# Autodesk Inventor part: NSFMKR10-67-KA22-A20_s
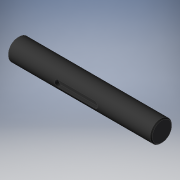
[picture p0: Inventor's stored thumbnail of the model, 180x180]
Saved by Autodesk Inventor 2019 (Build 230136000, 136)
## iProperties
Created: 2022-11
Part Number: NSFMKR10-67-KA22-A20_s
Material: Generic
Catalog Web Link: www.cadenas.de
Description: NSFMKR, SFMKR, PSFMKR, SSFMKR, NSFHKR, SFHKR, PSFHKR, SSFHKR, NSFGKR, SFGKR, PSFGKR, SSFGKR_shafts-Rotary Shafts - Straight with Keyway -
Vendor: MISUMI
Document SubType Name: Modeling
Designer: psAdmin
Manufacturer: MISUMI
Mass: 5.15435 g
Surface Area: 23.1132 cm^2
Volume: 5.15435 cm^3
Density: 1 g/cm^3
Appearance: PSOLRGB-175-175-175
Category: PARTsolutions
Company: MISUMI
Title: NSFMKR10-67-KA22-A20
Author: Cadenas PARTsolutions
Comments: Rotary Shafts - Straight with Keyway -
PSOL_IDENT_0: {$CADENAS_DATA/23d-libs/misumi/metric/11_rotary_shafts/11_components/psfgkr/psfgkr.prj},483 {VTYP=3D
PSOL_IDENT_1: },{NB=NSFMKR10-67-KA22-A20_s},{LINA=NSFMKR10-67-KA22-A20},{NN=NSFMKR, SFMKR, PSFMKR, SSFMKR, NSFHKR,
PSOL_IDENT_2: SFHKR, PSFHKR, SSFHKR, NSFGKR, SFGKR, PSFGKR, SSFGKR_shafts},{DATE=25.01.2022 23:09:52},{GEOMDATE=0
PSOL_IDENT_3: 5.02.2021 07:57:16},{VERSION=},{LINEID=30},{WBVAR=TS,MAT,ST,ALT1,L,NOK,KA,A,KB,B,KC,C,ALT3,FC,GALT3,
PSOL_IDENT_4: WFC,J,WALT3,V,ALT4,SFC,SGALT4,AG,ALT10,KWC,ALT11,WC,ALT6,TA,TB,ALT5,UC,ALT7,SC,ALT32,CD},{WBNUMERIC=
PSOL_IDENT_5: L,KA,A,KB,B,KC,C,FC,GALT3,WFC,J,WALT3,V,SFC,SGALT4,AG,KWC,WC,TA,TB,UC,SC}  {NB=NSFMKR10-67-KA22-A20_
PSOL_IDENT_6: s},{LINA=NSFMKR10-67-KA22-A20},{KT=DUMMY},{PN=NSFMKR10-67-KA22-A20},{TS=M},{TSALG= 'M','h9 (Cold-dra
PSOL_IDENT_7: wn)','H','h7 (Ground)','G','g6 (Ground)' },{MAT=S45C},{MATALG= 'S45C','S45C Equivalent', 'SUS304','S
PSOL_IDENT_8: US304' },{ST=},{STALG= '','-','BO','Black Oxide', 'ENP','Electroless Nickel Plating' },{TYPE=NSFMKR}
PSOL_IDENT_9: ,{D=10},{ALT1=},{L=67.0},{LALG=[15:800/0.1]},{LMIN=15},{LMAX=800},{NOK=1},{NOKALG= '1', 'with 1 Key
PSOL_IDENT_10: Groove', '2'  , 'with 2 Key Grooves', '3'  , 'with 3 Key Grooves'},{BB=3},{TT=1.8},{KA=22.0},{KAALG=
PSOL_IDENT_11: [0:64/0.1]},{KAMIN=0},{KAMAX1=64},{KAMAX2=59},{KAMAX3=54},{A=20.0},{AALG=[3:45/0.1]},{AMIN=3},{AMAX1=
PSOL_IDENT_12: 45},{AMAX2=40},{AMAX3=35},{KAPN=-KA22-A20},{KB=0.0},{KBALG=[0]},{KBMIN=44},{KBMAX1=64},{KBMAX2=59},{
PSOL_IDENT_13: B=0.0},{BALG=[0]},{BMIN=3},{BMAX1=67},{BMAX2=62},{KBPN=},{KC=0.0},{KCALG=[0]},{KCMIN=2},{KCMAX=64},{
PSOL_IDENT_14: C=0.0},{CALG=[0]},{CMIN=3},{CMAX=67},{KCPN=},{CIFKA=5},{CIFKB=3},{CIFKC=3},{ALT3=},{ALT3ALG= '', 'w/
PSOL_IDENT_15: o Set Screw Flat','FC','with FC (Adds a Set Screw Flat)','WFC','with WFC (Adds Two Set Screw Flats)'
PSOL_IDENT_16: ,'FCWFC','with FC + WFC (Adds Three Set Screw Flats)' },{ALT3PN=},{FC=0},{FCALG=[0]},{FCMIN=0},{FCMA
PSOL_IDENT_17: X=66},{GALT3=0},{GALT3ALG=[0]},{GALT3MIN=1},{GALT3MAX=67},{GALT3MAX2=61},{GALT3MAX3=64},{WFC=0},{WFC
PSOL_IDENT_18: ALG=[0]},{WFCMIN=0},{WFCMIN2=2},{WFCMAX=63},{WFCMAX2=-3},{WFCMAX3=-4},{J=0},{JALG=[0]},{JMIN=1},{JMA
PSOL_IDENT_19: X=64},{JMAX2=-2},{JMAX3=-5},{WALT3=0},{WALT3ALG=[0]},{WALT3MIN=0},{WALT3MIN2=69},{WALT3MAX=64},{WALT
PSOL_IDENT_20: 3MAX2=64},{V=0},{VALG=[0]},{VMIN=1},{VMAX=65},{VMAX3=65},{CIFFC=0},{ALT4=},{ALT4ALG= '', 'w/o SFC (2
PSOL_IDENT_21: Set Screw Flats (Angle Specified))', 'SFC' , 'with SFC (2 Set Screw Flats (Angle Specified))'},{ALT
PSOL_IDENT_22: 4PN=},{SFC=0},{SFCALG=[0]},{SFCMIN=0},{SFCMAX=66},{SGALT4=0},{SGALT4ALG=[0]},{SGALT4MIN=1},{SGALT4MA
PSOL_IDENT_23: X=50},{AG=0},{AGALG=[0]},{H=0},{CIFSFC=0},{ALT10=},{ALT10ALG= '', 'w/o KWC (2 Set Screw Flats at bot
PSOL_IDENT_24: h ends)', 'KWC', 'with KWC (2 Set Screw Flats at both ends)' },{ALT10PN=},{KWC=0},{KWCALG=[0]},{KWCM
PSOL_IDENT_25: IN=1},{KWCMAX=32.5},{WALT10=8},{ALT11=},{ALT11ALG= '','Not applicable' },{ALT11PN=},{WC=0.0},{WCALG=
PSOL_IDENT_26: [0]},{ALT6=},{ALT6ALG= '','w/o Retaining Ring Groove','TA','with TA (Retaining Ring Groove)','TB','w
PSOL_IDENT_27: ith TB (Retaining Ring Groove)','TATB','with TA + TB (Two Retaining Ring Grooves)' },{ALT6PN=},{TA=0
PSOL_IDENT_28: .0},{TAALG=[0]},{TAMIN=2},{TAMAX=0},{TB=0.0},{TBALG=[0]},{TBMIN=2},{TBMAX=0},{DDALT6=0.0},{MM=0.00},
PSOL_IDENT_29: {ALT5=},{ALT5ALG= '', 'w/o UC (Slit Cam Groove)', 'UC', 'with UC (Slit Cam Groove)'},{ALT5PN=},{UC=0
PSOL_IDENT_30: },{UCALG=[0]},{UCMIN=1},{UCMAX=61},{DD=0},{LL1=0},{ALT7=},{ALT7ALG= '', 'w/o SC (Wrench Flats)', 'SC'
PSOL_IDENT_31: , 'with SC (Wrench Flats)'},{ALT7PN=},{SC=0},{SCALG=[0]},{SCMIN=0},{SCMAX=59},{WALT7=0},{LL2=0},{LL2
PSOL_IDENT_32: ALG=8},{CIFSC=0},{ALT32=},{ALT32ALG=  '','w/o CD (Changes Part D Chamfering)','CD', 'with CD (Change
PSOL_IDENT_33: s Part D Chamfering)' },{ALT32PN=},{CD=},{CDALG= '','' },{CD3D=0.5},{CIF32=0},{CIF320=0},{CIF32FC=0}
PSOL_IDENT_34: ,{CIF32WFC=0},{CIF32WALT3=0},{ERRORPN=},{ERRORKGALT3=OK},{ERRORKGALT4=OK},{ERRORKGALT5=OK},{ERRORKGA
PSOL_IDENT_35: LT7=OK},{ERRORKGALT10=OK},{ERRORALT34=OK},{ERRORALT35=OK},{ERRORALT37=OK},{ERRORALT310=OK},{ERRORALT
PSOL_IDENT_36: 45=OK},{ERRORALT47=OK},{ERRORALT410=OK},{ERRORALT57=OK},{ERRORALT510=OK},{ERRORALT710=OK},{ERRORALT3
PSOL_IDENT_37: 6=OK},{ERRORALT46=OK},{ERRORALT56=OK},{ERRORALT67=OK},{ERRORALT610=OK},{ERRORKGALT6=OK},{CIFTA=0},{C
PSOL_IDENT_38: IFTB=0}
NB: NSFMKR10-67-KA22-A20_s
NN: NSFMKR, SFMKR, PSFMKR, SSFMKR, NSFHKR, SFHKR, PSFHKR, SSFHKR, NSFGKR, SFGKR, PSFGKR, SSFGKR_shafts
NT: Rotary Shafts - Straight with Keyway -
NBSYN: $PN._s
LINA: NSFMKR10-67-KA22-A20
CATALOG: Misumi
PN: NSFMKR10-67-KA22-A20
TS: h9 (Cold-drawn)
MAT: S45C Equivalent
ST: -
D: 10
ALT1: w/o LKC (Changes L Tolerance)
L: 67
NOK: with 1 Key Groove
KA: 22
A: 20
KB: 0
B: 0
KC: 0
C: 0
ALT3: w/o Set Screw Flat
FC: 0
GALT3: 0
WFC: 0
J: 0
WALT3: 0
V: 0
ALT4: w/o SFC (2 Set Screw Flats (Angle Specified))
SFC: 0
SGALT4: 0
AG: 0
H: 0
ALT10: w/o KWC (2 Set Screw Flats at both ends)
KWC: 0
ALT11: Not applicable
WC: 0
ALT6: w/o Retaining Ring Groove
TA: 0
TB: 0
DDALT6: 0
MM: 0
ALT5: w/o UC (Slit Cam Groove)
UC: 0
LL1: 0
ALT7: w/o SC (Wrench Flats)
SC: 0
WALT7: 0
LL2: 0
ALT32: w/o CD (Changes Part D Chamfering)
SUPPLIER: MISUMI
ARTICLENO: NSFMKR10-67-KA22-A20_s
BOMINFO: NSFMKR10-67-KA22-A20
CREATOR: CADENAS GmbH
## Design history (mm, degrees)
sketch "Sketch_1"
  geometry: L1 (-67, 0)-(0, 0); L2 (0, 0)-(0, -4.5); L3 (0, -4.5)-(-0.5, -5); L4 (-0.5, -5)-(-66.5, -5); L5 (-66.5, -5)-(-67, -4.5); L6 (-67, -4.5)-(-67, 0); L7 (-67, 0)-(0, 0)
  constraints: 14 end point
revolve "Revolution1" sketch "Sketch_1" stored, may be unused: angle "d0" = 360 deg
sketch "_____13"
  geometry: L1 (23.5, -1.5)-(40.5, -1.5); L2 (40.5, 1.5)-(23.5, 1.5); A1 r 1.5 centre (23.5, 0) between (23.5, 1.5) and (23.5, -1.5); A2 r 1.5 centre (40.5, 0) between (40.5, -1.5) and (40.5, 1.5)
  constraints: 4 end point, 4 point on circle, 2 centre point
extrude "Extrusion1" cut sketch "_____13" distance "d1" = 1.8; taper "d2" = 0 deg
body "Solid1"
